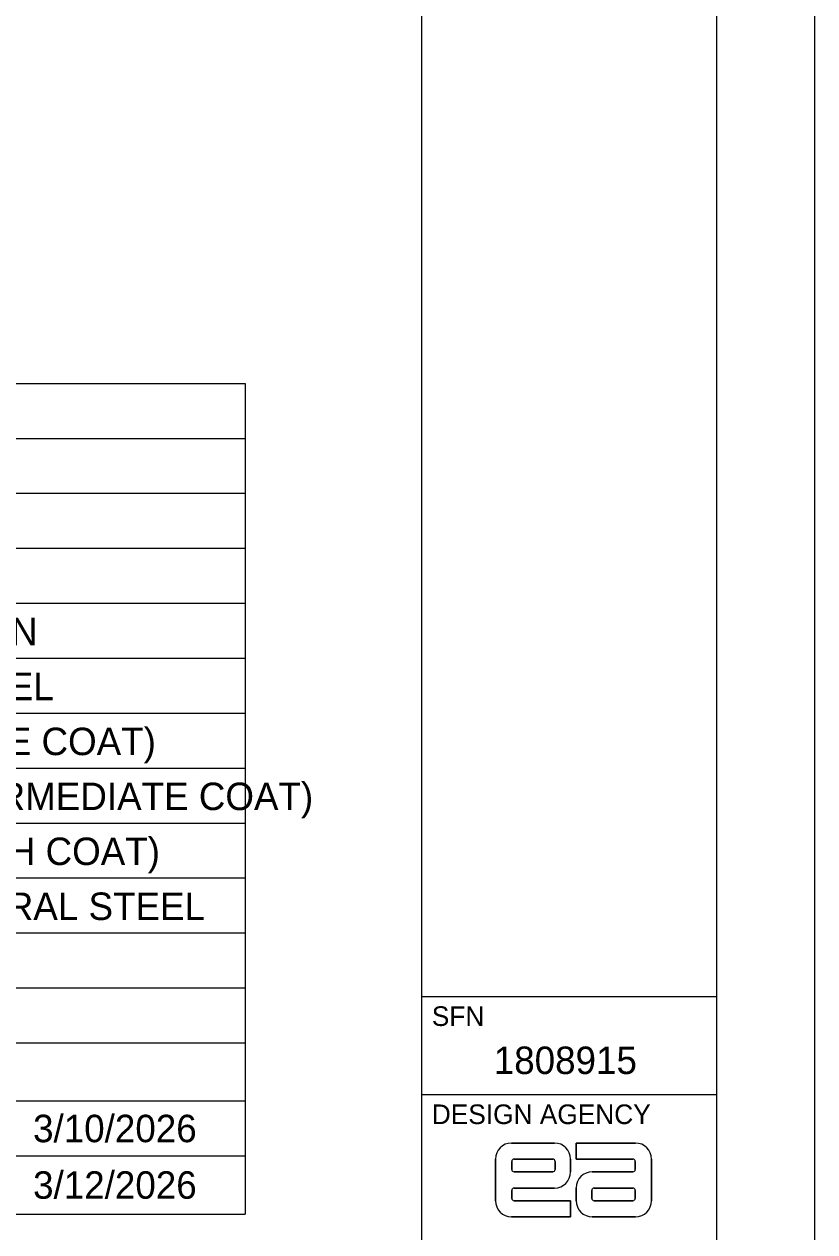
# Model space of a CAD drawing. Extents: x 0 to 34, y 0 to 22.
# Drawn here: x 29.97 to 34, y 4.3 to 10.45 of the extents above; entities that cross this region are included whole.
import ezdxf

# ---------------------------------------------------------------- set-up
doc = ezdxf.new("R2010")
doc.units = 0
for name, color, linetype in [('SH_Border', 7, 'Continuous'), ('SH_Cut_Line', 7, 'Continuous'), ('SH_Data', 7, 'Continuous'), ('SH_Text', 7, 'Continuous'), ('TX_X_20', 7, 'Continuous')]:
    doc.layers.add(name, color=color, linetype=linetype)

msp = doc.modelspace()

# ---------------------------------------------------------------- linework, layer by layer
at = {"layer": 'SH_Border'}
for p, q in [((32, 0.5), (32, 21.5)), ((32, 5.5), (33.5, 5.5)), ((32, 5), (33.5, 5))]:
    msp.add_line(p, q, dxfattribs=at)
msp.add_lwpolyline([(1.5, 21.5), (33.5, 21.5), (33.5, 0.5), (1.5, 0.5)], close=True, dxfattribs=at)
at = {"layer": 'SH_Cut_Line'}
msp.add_lwpolyline([(0, 0), (34, 0), (34, 22), (0, 22)], close=True, dxfattribs=at)
at = {"layer": 'SH_Text'}
for p, q in [((21.2176, 8.6241), (31.1, 8.6241)), ((31.1, 8.6241), (31.1, 4.9676)), ((21.2176, 8.3441), (31.1, 8.3441)), ((21.2176, 8.0641), (31.1, 8.0641)), ((21.2176, 7.7841), (31.1, 7.7841)), ((21.2176, 7.5041), (31.1, 7.5041)), ((21.2176, 7.2241), (31.1, 7.2241)), ((21.2176, 6.9441), (31.1, 6.9441)), ((21.2176, 6.6641), (31.1, 6.6641)), ((21.2176, 6.3841), (31.1, 6.3841)), ((21.2176, 6.1041), (31.1, 6.1041)), ((21.2176, 5.8241), (31.1, 5.8241)), ((21.2176, 5.5441), (31.1, 5.5441)), ((21.2176, 5.2641), (31.1, 5.2641)), ((21.2176, 4.9676), (31.1, 4.9676)), ((27.3941, 4.9676), (31.1, 4.9676)), ((31.1, 4.9676), (31.1, 4.3911)), ((27.3941, 4.6876), (31.1, 4.6876)), ((27.3941, 4.3911), (31.1, 4.3911))]:
    msp.add_line(p, q, dxfattribs=at)
at = {"layer": 'TX_X_20'}
for p, q in [((32.6745, 4.7533), (32.456, 4.7533)), ((32.456, 4.7533), (32.6745, 4.7533)), ((32.785, 4.7533), (33.0865, 4.7533)), ((32.785, 4.6713), (32.785, 4.7533)), ((32.3739, 4.6713), (32.3739, 4.4597)), ((32.3739, 4.4597), (32.3739, 4.6713)), ((32.457, 4.6189), (32.457, 4.6594)), ((32.457, 4.6594), (32.457, 4.6189)), ((32.4688, 4.6713), (32.6656, 4.6713)), ((32.6656, 4.6713), (32.4688, 4.6713)), ((32.6775, 4.6594), (32.6775, 4.6189)), ((32.6775, 4.6189), (32.6775, 4.6594)), ((32.7566, 4.606), (32.7566, 4.6713)), ((32.7566, 4.6713), (32.7566, 4.606)), ((33.0737, 4.6713), (32.785, 4.6713)), ((33.0855, 4.6594), (33.0855, 4.6189)), ((33.0855, 4.6189), (33.0855, 4.6594)), ((33.1686, 4.4597), (33.1686, 4.6713)), ((33.1686, 4.6713), (33.1686, 4.4597)), ((32.6656, 4.607), (32.4688, 4.607)), ((32.4688, 4.607), (32.6656, 4.607)), ((33.0737, 4.607), (32.8671, 4.607)), ((32.8671, 4.607), (33.0737, 4.607)), ((32.457, 4.4716), (32.457, 4.5121)), ((32.457, 4.5121), (32.457, 4.4716)), ((32.4688, 4.524), (32.6745, 4.524)), ((32.6745, 4.524), (32.4688, 4.524)), ((32.785, 4.525), (32.785, 4.4597)), ((32.785, 4.4597), (32.785, 4.525)), ((32.8641, 4.4716), (32.8641, 4.5121)), ((32.8641, 4.5121), (32.8641, 4.4716)), ((32.876, 4.524), (33.0737, 4.524)), ((33.0737, 4.524), (32.876, 4.524)), ((33.0855, 4.5121), (33.0855, 4.4716)), ((33.0855, 4.4716), (33.0855, 4.5121)), ((32.4688, 4.4597), (32.7566, 4.4597)), ((32.7566, 4.4597), (32.7566, 4.3777)), ((33.0737, 4.4597), (32.876, 4.4597)), ((32.876, 4.4597), (33.0737, 4.4597)), ((32.7566, 4.3777), (32.456, 4.3777)), ((32.8671, 4.3777), (33.0865, 4.3777)), ((33.0865, 4.3777), (32.8671, 4.3777))]:
    msp.add_line(p, q, dxfattribs=at)
for points in [[(33.0865, 4.7533), (32.785, 4.7533), (32.785, 4.6713), (33.0737, 4.6713)], [(32.456, 4.3777), (32.7566, 4.3777), (32.7566, 4.4597), (32.4688, 4.4597)]]:
    msp.add_lwpolyline(points, dxfattribs=at)
for centre, radius, start, end in [((32.456, 4.6713), 0.0821, 90, 180), ((32.456, 4.6713), 0.0821, 90, 180), ((32.6745, 4.6713), 0.0821, 0, 90), ((32.6745, 4.6713), 0.0821, 0, 90), ((33.0865, 4.6713), 0.0821, 0, 90), ((33.0865, 4.6713), 0.0821, 0, 90), ((32.4688, 4.6594), 0.0119, 90, 180), ((32.4688, 4.6594), 0.0119, 90, 180), ((32.4688, 4.6189), 0.0119, 180, 270), ((32.4688, 4.6189), 0.0119, 180, 270), ((32.6656, 4.6594), 0.0119, 0, 90), ((32.6656, 4.6594), 0.0119, 0, 90), ((32.6656, 4.6189), 0.0119, 270, 0), ((32.6656, 4.6189), 0.0119, 270, 0), ((33.0737, 4.6594), 0.0119, 0, 90), ((33.0737, 4.6594), 0.0119, 0, 90), ((33.0737, 4.6189), 0.0119, 270, 0), ((33.0737, 4.6189), 0.0119, 270, 0), ((32.6745, 4.606), 0.0821, 270, 360), ((32.6745, 4.606), 0.0821, 270, 360), ((32.8671, 4.525), 0.0821, 90, 180), ((32.8671, 4.525), 0.0821, 90, 180), ((32.4688, 4.5121), 0.0119, 90, 180), ((32.4688, 4.5121), 0.0119, 90, 180), ((32.876, 4.5121), 0.0119, 90, 180), ((32.876, 4.5121), 0.0119, 90, 180), ((33.0737, 4.5121), 0.0119, 0, 90), ((33.0737, 4.5121), 0.0119, 0, 90), ((32.456, 4.4597), 0.0821, 180, 270), ((32.456, 4.4597), 0.0821, 180, 270), ((32.4688, 4.4716), 0.0119, 180, 270), ((32.4688, 4.4716), 0.0119, 180, 270), ((32.8671, 4.4597), 0.0821, 180, 270), ((32.8671, 4.4597), 0.0821, 180, 270), ((32.876, 4.4716), 0.0119, 180, 270), ((32.876, 4.4716), 0.0119, 180, 270), ((33.0737, 4.4716), 0.0119, 270, 0), ((33.0737, 4.4716), 0.0119, 270, 0), ((33.0865, 4.4597), 0.0821, 270, 360), ((33.0865, 4.4597), 0.0821, 270, 360)]:
    msp.add_arc(centre, radius, start, end, dxfattribs=at)

# ---------------------------------------------------------------- texts
at = {"layer": 'SH_Data'}
for s, height, p in [('SFN', 0.1, (32.05, 5.35)), ('1808915', 0.14, (32.3654, 5.105)), ('DESIGN AGENCY', 0.1, (32.05, 4.85))]:
    msp.add_text(s, height=height, dxfattribs=at).set_placement(p)
at = {"layer": 'SH_Text'}
for s, p in [('STRUCTURAL STEEL  MEMEBERS, LEVEL UF, AS PER PLAN', (24.6435, 7.29)), ('SURFACE PREPARATION OF EXISTING STRUCTURAL STEEL', (24.6435, 7.01)), ('FIELD PAINTING OF EXISTING STRUCTURAL STEEL (PRIME COAT)', (24.6435, 6.73)), ('FIELD PAINTING OF EXISTING STRUCTURAL STEEL (INTERMEDIATE COAT)', (24.6435, 6.45)), ('FIELD PAINTING OF EXISTING STRUCTURAL STEEL (FINISH COAT)', (24.6435, 6.17)), ('GRINDING FINS, TEARS, SLIVERS ON EXISTING STRUCTURAL STEEL', (24.6435, 5.89)), ('3/10/2026', (30.0201, 4.7576)), ('3/12/2026', (30.0201, 4.4694))]:
    msp.add_text(s, height=0.14, dxfattribs=at).set_placement(p)

doc.saveas('drawing.dxf')
